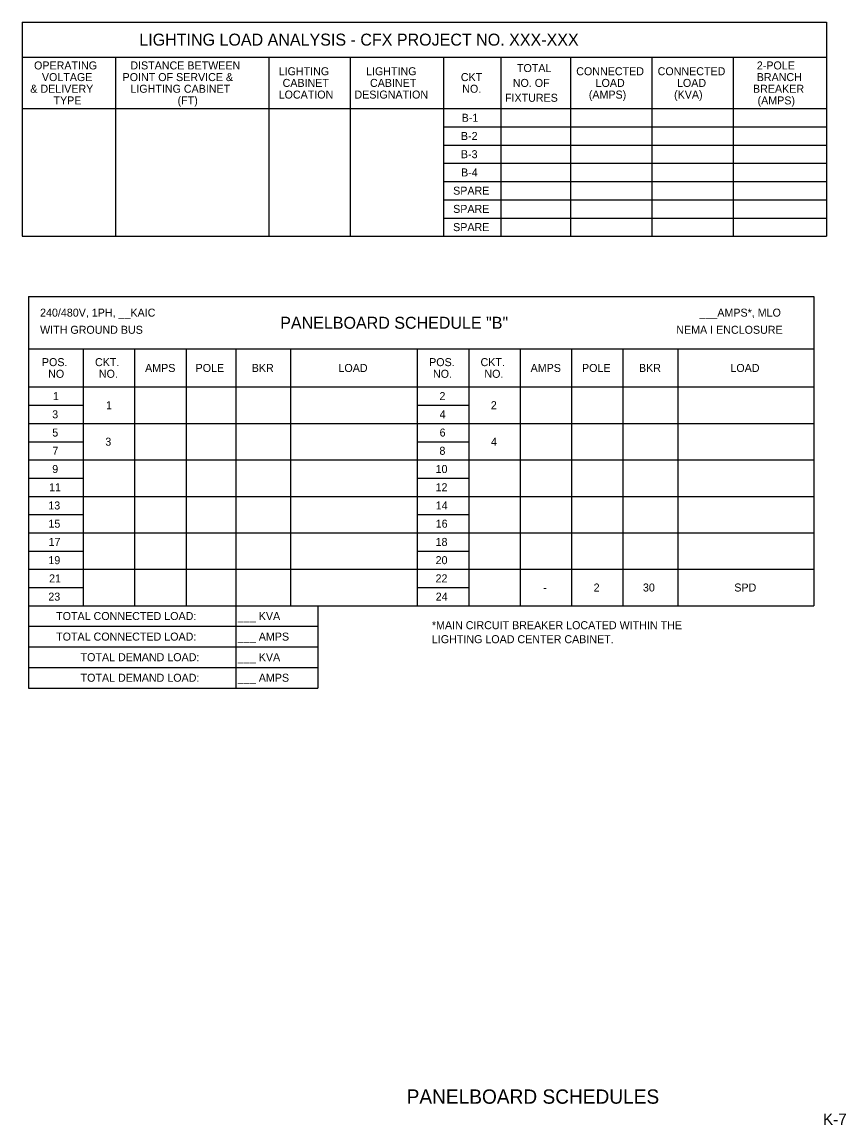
# Model space of a CAD drawing. Extents: x 856079 to 2148480, y 462635 to 2147771.
# Drawn here: x 2148473.14 to 2148480.35, y 2147761.82 to 2147771.47 of the extents above; entities that cross this region are included whole.
import ezdxf

# ---------------------------------------------------------------- set-up
doc = ezdxf.new("R2010")
doc.units = 0
for name, color, linetype in [('FLMap5', 7, 'Continuous'), ('NonPlottingEle_dp', 7, 'Continuous'), ('SignPanel', 7, 'Continuous'), ('SumBoxBorder_dp', 7, 'Continuous'), ('SumBoxLines_dp', 7, 'Continuous'), ('TextNotes', 7, 'Continuous')]:
    doc.layers.add(name, color=color, linetype=linetype)

msp = doc.modelspace()

# ---------------------------------------------------------------- linework, layer by layer
at = {"layer": 'SumBoxBorder_dp'}
for p, q in [((2148473.1374, 2147771.4724), (2148480.1799, 2147771.4724)), ((2148473.1374, 2147771.4724), (2148473.1374, 2147769.5984)), ((2148480.1799, 2147771.4724), (2148480.1799, 2147769.5984)), ((2148473.1374, 2147771.1649), (2148480.1799, 2147771.1649)), ((2148473.1374, 2147771.1649), (2148480.1799, 2147771.1649)), ((2148473.1374, 2147769.5984), (2148480.1799, 2147769.5984)), ((2148473.1927, 2147769.0699), (2148480.0702, 2147769.0699)), ((2148473.1927, 2147769.0699), (2148473.1927, 2147765.6454)), ((2148480.0702, 2147769.0699), (2148480.0702, 2147766.3654)), ((2148473.1927, 2147768.6124), (2148480.0702, 2147768.6124)), ((2148473.1927, 2147768.6124), (2148480.0702, 2147768.6124)), ((2148473.1927, 2147766.3654), (2148480.0702, 2147766.3654)), ((2148473.1927, 2147766.3654), (2148480.0702, 2147766.3654)), ((2148475.0077, 2147766.3654), (2148475.0077, 2147765.6454)), ((2148475.7277, 2147766.3654), (2148475.7277, 2147765.6454)), ((2148475.7277, 2147766.3654), (2148475.7277, 2147765.6454)), ((2148473.1927, 2147766.1854), (2148475.7277, 2147766.1854)), ((2148473.1927, 2147766.1854), (2148475.7277, 2147766.1854)), ((2148473.1927, 2147766.0054), (2148475.7277, 2147766.0054)), ((2148473.1927, 2147766.0054), (2148475.7277, 2147766.0054)), ((2148473.1927, 2147765.8254), (2148475.7277, 2147765.8254)), ((2148473.1927, 2147765.8254), (2148475.7277, 2147765.8254)), ((2148473.1927, 2147765.6454), (2148475.7277, 2147765.6454))]:
    msp.add_line(p, q, dxfattribs=at)
at = {"layer": 'SumBoxLines_dp'}
for p, q in [((2148473.9549, 2147771.1649), (2148473.9549, 2147769.5984)), ((2148473.9549, 2147771.1649), (2148473.9549, 2147769.5984)), ((2148475.2974, 2147771.1649), (2148475.2974, 2147769.5984)), ((2148475.2974, 2147771.1649), (2148475.2974, 2147769.5984)), ((2148476.0099, 2147771.1649), (2148476.0099, 2147769.5984)), ((2148476.0099, 2147771.1649), (2148476.0099, 2147769.5984)), ((2148476.8274, 2147771.1649), (2148476.8274, 2147769.5984)), ((2148476.8274, 2147771.1649), (2148476.8274, 2147769.5984)), ((2148477.3299, 2147771.1649), (2148477.3299, 2147769.5984)), ((2148477.3299, 2147771.1649), (2148477.3299, 2147769.5984)), ((2148477.9374, 2147771.1649), (2148477.9374, 2147769.5984)), ((2148477.9374, 2147771.1649), (2148477.9374, 2147769.5984)), ((2148478.6499, 2147771.1649), (2148478.6499, 2147769.5984)), ((2148478.6499, 2147771.1649), (2148478.6499, 2147769.5984)), ((2148479.3624, 2147771.1649), (2148479.3624, 2147769.5984)), ((2148479.3624, 2147771.1649), (2148479.3624, 2147769.5984)), ((2148473.1374, 2147770.7149), (2148480.1799, 2147770.7149)), ((2148473.1374, 2147770.7149), (2148480.1799, 2147770.7149)), ((2148476.8274, 2147770.5554), (2148480.1799, 2147770.5554)), ((2148476.8274, 2147770.5554), (2148480.1799, 2147770.5554)), ((2148476.8274, 2147770.3959), (2148480.1799, 2147770.3959)), ((2148476.8274, 2147770.3959), (2148480.1799, 2147770.3959)), ((2148476.8274, 2147770.2364), (2148480.1799, 2147770.2364)), ((2148476.8274, 2147770.2364), (2148480.1799, 2147770.2364)), ((2148476.8274, 2147770.0769), (2148480.1799, 2147770.0769)), ((2148476.8274, 2147770.0769), (2148480.1799, 2147770.0769)), ((2148476.8274, 2147769.9174), (2148480.1799, 2147769.9174)), ((2148476.8274, 2147769.9174), (2148480.1799, 2147769.9174)), ((2148476.8274, 2147769.7579), (2148480.1799, 2147769.7579)), ((2148476.8274, 2147769.7579), (2148480.1799, 2147769.7579)), ((2148473.6727, 2147768.6124), (2148473.6727, 2147766.3654)), ((2148473.6727, 2147768.6124), (2148473.6727, 2147766.3654)), ((2148474.1227, 2147768.6124), (2148474.1227, 2147766.3654)), ((2148474.1227, 2147768.6124), (2148474.1227, 2147766.3654)), ((2148474.5727, 2147768.6124), (2148474.5727, 2147766.3654)), ((2148474.5727, 2147768.6124), (2148474.5727, 2147766.3654)), ((2148475.0077, 2147768.6124), (2148475.0077, 2147766.3654)), ((2148475.0077, 2147768.6124), (2148475.0077, 2147766.3654)), ((2148475.4877, 2147768.6124), (2148475.4877, 2147766.3654)), ((2148475.4877, 2147768.6124), (2148475.4877, 2147766.3654)), ((2148476.5977, 2147768.6124), (2148476.5977, 2147766.3654)), ((2148476.5977, 2147768.6124), (2148476.5977, 2147766.3654)), ((2148477.0477, 2147768.6124), (2148477.0477, 2147766.3654)), ((2148477.0477, 2147768.6124), (2148477.0477, 2147766.3654)), ((2148477.4977, 2147768.6124), (2148477.4977, 2147766.3654)), ((2148477.4977, 2147768.6124), (2148477.4977, 2147766.3654)), ((2148477.9477, 2147768.6124), (2148477.9477, 2147766.3654)), ((2148477.9477, 2147768.6124), (2148477.9477, 2147766.3654)), ((2148478.3977, 2147768.6124), (2148478.3977, 2147766.3654)), ((2148478.3977, 2147768.6124), (2148478.3977, 2147766.3654)), ((2148478.8777, 2147768.6124), (2148478.8777, 2147766.3654)), ((2148478.8777, 2147768.6124), (2148478.8777, 2147766.3654)), ((2148473.1927, 2147768.2794), (2148480.0702, 2147768.2794)), ((2148473.1927, 2147768.2794), (2148480.0702, 2147768.2794)), ((2148473.1927, 2147768.1199), (2148473.6727, 2147768.1199)), ((2148473.1927, 2147768.1199), (2148473.6727, 2147768.1199)), ((2148476.5977, 2147768.1199), (2148477.0477, 2147768.1199)), ((2148473.1927, 2147767.9604), (2148480.0702, 2147767.9604)), ((2148473.1927, 2147767.9604), (2148480.0702, 2147767.9604)), ((2148473.1927, 2147767.8009), (2148473.6727, 2147767.8009)), ((2148473.1927, 2147767.8009), (2148473.6727, 2147767.8009)), ((2148476.5977, 2147767.8009), (2148477.0477, 2147767.8009)), ((2148476.5977, 2147767.8009), (2148477.0477, 2147767.8009)), ((2148473.1927, 2147767.6414), (2148476.5977, 2147767.6414)), ((2148473.1927, 2147767.6414), (2148480.0702, 2147767.6414)), ((2148477.0477, 2147767.6414), (2148480.0702, 2147767.6414)), ((2148473.1927, 2147767.4819), (2148473.6727, 2147767.4819)), ((2148473.1927, 2147767.4819), (2148473.6727, 2147767.4819)), ((2148476.5977, 2147767.4819), (2148477.0477, 2147767.4819)), ((2148476.5977, 2147767.4819), (2148477.0477, 2147767.4819)), ((2148473.1927, 2147767.3224), (2148480.0702, 2147767.3224)), ((2148473.1927, 2147767.3224), (2148480.0702, 2147767.3224)), ((2148473.1927, 2147767.1629), (2148473.6727, 2147767.1629)), ((2148473.1927, 2147767.1629), (2148473.6727, 2147767.1629)), ((2148476.5977, 2147767.1629), (2148477.0477, 2147767.1629)), ((2148473.1927, 2147767.0034), (2148480.0702, 2147767.0034)), ((2148473.1927, 2147767.0034), (2148480.0702, 2147767.0034)), ((2148473.1927, 2147766.8439), (2148473.6727, 2147766.8439)), ((2148473.1927, 2147766.8439), (2148473.6727, 2147766.8439)), ((2148476.5977, 2147766.8439), (2148477.0477, 2147766.8439)), ((2148476.5977, 2147766.8439), (2148477.0477, 2147766.8439)), ((2148473.1927, 2147766.6844), (2148476.5977, 2147766.6844)), ((2148473.1927, 2147766.6844), (2148480.0702, 2147766.6844)), ((2148477.0477, 2147766.6844), (2148480.0702, 2147766.6844)), ((2148473.1927, 2147766.5249), (2148473.6727, 2147766.5249)), ((2148473.1927, 2147766.5249), (2148473.6727, 2147766.5249)), ((2148476.5977, 2147766.5249), (2148477.0477, 2147766.5249)), ((2148476.5977, 2147766.5249), (2148477.0477, 2147766.5249))]:
    msp.add_line(p, q, dxfattribs=at)

# ---------------------------------------------------------------- texts
at = {"layer": 'FLMap5'}
for s, height, p in [('LIGHTING LOAD ANALYSIS - CFX PROJECT NO. XXX-XXX', 0.105, (2148474.1638, 2147771.2662)), ('OPERATING', 0.07, (2148473.2425, 2147771.0579)), ('DISTANCE BETWEEN', 0.07, (2148474.0854, 2147771.0579)), ('LIGHTING', 0.07, (2148475.3839, 2147771.0069)), ('LIGHTING', 0.07, (2148476.1489, 2147771.0069)), ('TOTAL', 0.07, (2148477.47, 2147771.0349)), ('CONNECTED', 0.07, (2148477.989, 2147771.0069)), ('CONNECTED', 0.07, (2148478.7015, 2147771.0069)), ('2-POLE', 0.07, (2148479.5701, 2147771.0579)), ('VOLTAGE', 0.07, (2148473.3112, 2147770.9559)), ('POINT OF SERVICE &', 0.07, (2148474.0176, 2147770.9559)), ('CABINET', 0.07, (2148475.4183, 2147770.9049)), ('CABINET', 0.07, (2148476.1833, 2147770.9049)), ('CKT', 0.07, (2148476.9788, 2147770.9559)), ('NO. OF', 0.07, (2148477.4336, 2147770.9049)), ('LOAD', 0.07, (2148478.1584, 2147770.9049)), ('LOAD', 0.07, (2148478.8709, 2147770.9049)), ('BRANCH', 0.07, (2148479.5692, 2147770.9559)), ('& DELIVERY', 0.07, (2148473.2097, 2147770.8539)), ('LIGHTING CABINET', 0.07, (2148474.0859, 2147770.8539)), ('NO.', 0.07, (2148476.991, 2147770.8539)), ('(AMPS)', 0.07, (2148478.099, 2147770.8029)), ('(KVA)', 0.07, (2148478.8454, 2147770.8029)), ('BREAKER', 0.07, (2148479.5362, 2147770.8539)), ('TYPE', 0.07, (2148473.4128, 2147770.7519)), ('(FT)', 0.07, (2148474.4993, 2147770.7519)), ('LOCATION', 0.07, (2148475.3839, 2147770.8029)), ('DESIGNATION', 0.07, (2148476.0473, 2147770.8029)), ('FIXTURES', 0.07, (2148477.365, 2147770.7749)), ('(AMPS)', 0.07, (2148479.5765, 2147770.7519)), ('B-1', 0.07, (2148476.9862, 2147770.6002)), ('B-2', 0.07, (2148476.9795, 2147770.4407)), ('B-3', 0.07, (2148476.9794, 2147770.2812)), ('B-4', 0.07, (2148476.9808, 2147770.1217)), ('SPARE', 0.07, (2148476.9115, 2147769.9622)), ('SPARE', 0.07, (2148476.9115, 2147769.8027)), ('SPARE', 0.07, (2148476.9115, 2147769.6432)), ('240/480V, 1PH, __KAIC', 0.07, (2148473.2952, 2147768.8949)), ('___AMPS*, MLO', 0.07, (2148479.0678, 2147768.8949)), ('PANELBOARD SCHEDULE "B"', 0.105, (2148475.3974, 2147768.7887)), ('WITH GROUND BUS', 0.07, (2148473.2952, 2147768.7449)), ('NEMA I ENCLOSURE', 0.07, (2148478.865, 2147768.7449)), ('POS.', 0.07, (2148473.3112, 2147768.4619)), ('CKT.', 0.07, (2148473.7762, 2147768.4619)), ('AMPS', 0.07, (2148474.2146, 2147768.4109)), ('POLE', 0.07, (2148474.6569, 2147768.4109)), ('BKR', 0.07, (2148475.1482, 2147768.4109)), ('LOAD', 0.07, (2148475.9075, 2147768.4109)), ('POS.', 0.07, (2148476.7012, 2147768.4619)), ('CKT.', 0.07, (2148477.1512, 2147768.4619)), ('AMPS', 0.07, (2148477.5896, 2147768.4109)), ('POLE', 0.07, (2148478.0394, 2147768.4109)), ('BKR', 0.07, (2148478.5382, 2147768.4109)), ('LOAD', 0.07, (2148479.3387, 2147768.4109)), ('NO', 0.07, (2148473.3659, 2147768.3599)), ('NO.', 0.07, (2148473.81, 2147768.3599)), ('NO.', 0.07, (2148476.735, 2147768.3599)), ('NO.', 0.07, (2148477.185, 2147768.3599)), ('1', 0.07, (2148473.408, 2147768.1647)), ('2', 0.07, (2148476.7913, 2147768.1647)), ('1', 0.07, (2148473.873, 2147768.0849)), ('2', 0.07, (2148477.2413, 2147768.0849)), ('3', 0.07, (2148473.4013, 2147768.0052)), ('4', 0.07, (2148476.7927, 2147768.0052)), ('5', 0.07, (2148473.4022, 2147767.8457)), ('6', 0.07, (2148476.7927, 2147767.8457)), ('3', 0.07, (2148473.8663, 2147767.7659)), ('4', 0.07, (2148477.2427, 2147767.7659)), ('7', 0.07, (2148473.4033, 2147767.6862)), ('8', 0.07, (2148476.7915, 2147767.6862)), ('9', 0.07, (2148473.4017, 2147767.5267)), ('10', 0.07, (2148476.758, 2147767.5267)), ('11', 0.07, (2148473.3742, 2147767.3672)), ('12', 0.07, (2148476.7574, 2147767.3672)), ('13', 0.07, (2148473.3674, 2147767.2077)), ('14', 0.07, (2148476.7588, 2147767.2077)), ('15', 0.07, (2148473.3683, 2147767.0482)), ('16', 0.07, (2148476.7588, 2147767.0482)), ('17', 0.07, (2148473.3694, 2147766.8887)), ('18', 0.07, (2148476.7577, 2147766.8887)), ('19', 0.07, (2148473.3678, 2147766.7292)), ('20', 0.07, (2148476.758, 2147766.7292)), ('21', 0.07, (2148473.3742, 2147766.5697)), ('22', 0.07, (2148476.7574, 2147766.5697)), ('2', 0.07, (2148478.1413, 2147766.4899)), ('30', 0.07, (2148478.573, 2147766.4899)), ('SPD', 0.07, (2148479.3726, 2147766.4899)), ('23', 0.07, (2148473.3674, 2147766.4102)), ('24', 0.07, (2148476.7588, 2147766.4102)), ('-', 0.07, (2148477.6992, 2147766.4899)), ('TOTAL CONNECTED LOAD:', 0.07, (2148473.4358, 2147766.2404)), ('___ KVA', 0.07, (2148475.0277, 2147766.2404)), ('TOTAL CONNECTED LOAD:', 0.07, (2148473.4358, 2147766.0604)), ('___ AMPS', 0.07, (2148475.0277, 2147766.0604)), ('TOTAL DEMAND LOAD:', 0.07, (2148473.6498, 2147765.8804)), ('___ KVA', 0.07, (2148475.0277, 2147765.8804)), ('TOTAL DEMAND LOAD:', 0.07, (2148473.6498, 2147765.7004)), ('___ AMPS', 0.07, (2148475.0277, 2147765.7004))]:
    msp.add_text(s, height=height, dxfattribs=at).set_placement(p)
at = {"layer": 'NonPlottingEle_dp'}
msp.add_text('K-7', height=0.1, dxfattribs=at).set_placement((2148480.1488, 2147761.8225))
at = {"layer": 'SignPanel'}
msp.add_text('     PANELBOARD SCHEDULES      ', height=0.125, dxfattribs=at).set_placement((2148476.272, 2147762.0082))
at = {"layer": 'TextNotes'}
for s, p in [('*MAIN CIRCUIT BREAKER LOCATED WITHIN THE', (2148476.7253, 2147766.1602)), ('LIGHTING LOAD CENTER CABINET.', (2148476.7253, 2147766.0377))]:
    msp.add_text(s, height=0.07, dxfattribs=at).set_placement(p)

doc.saveas('drawing.dxf')
